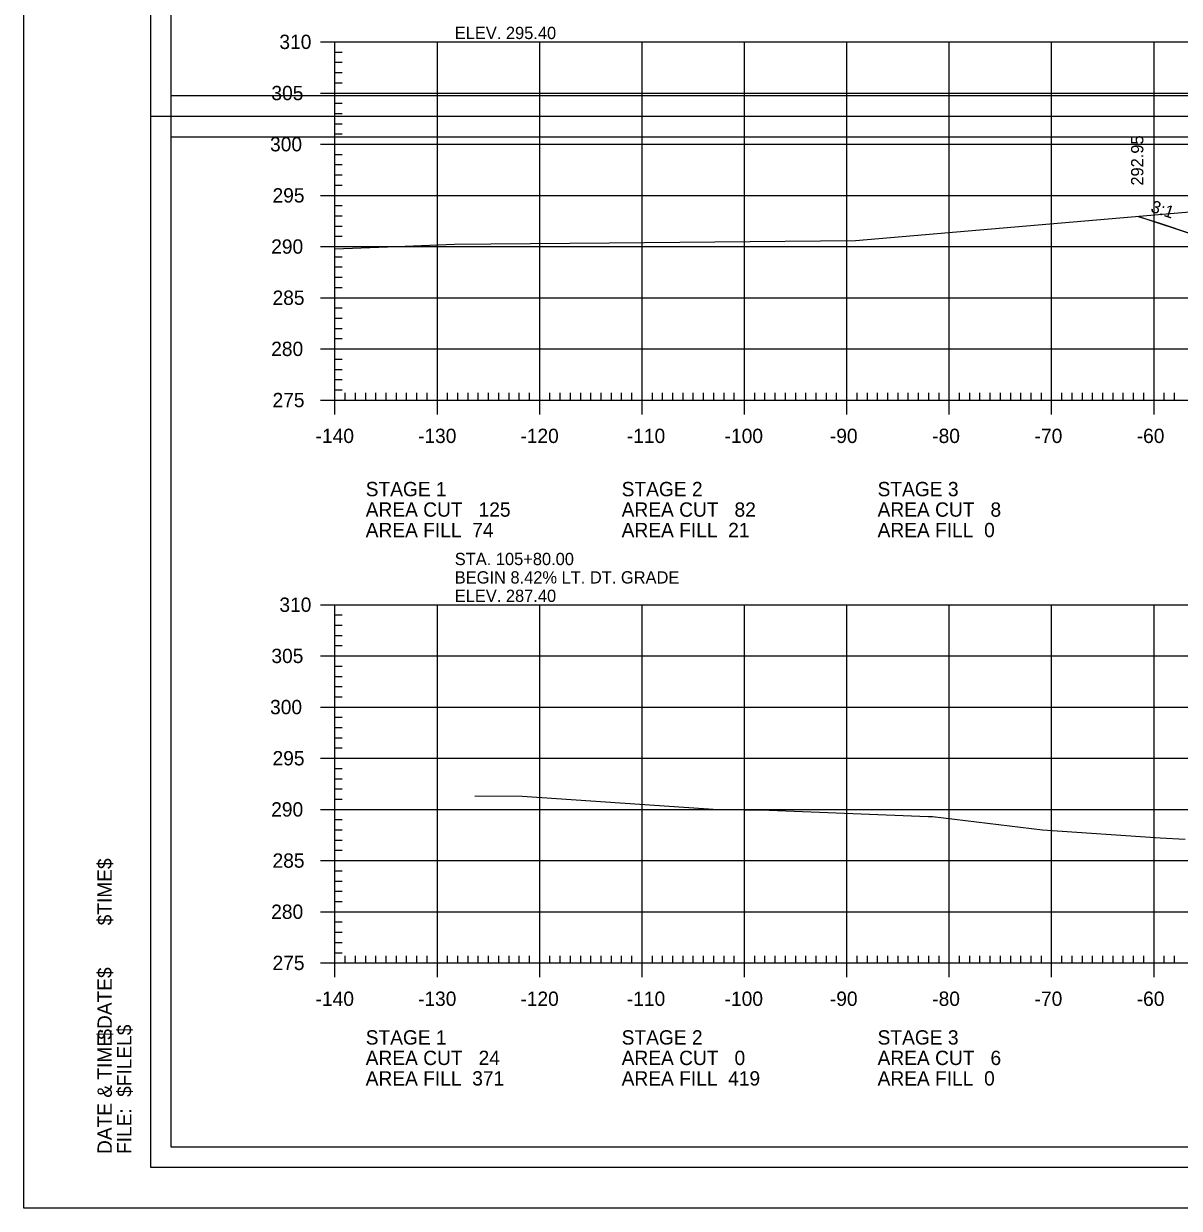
# Model space of a CAD drawing. Extents: x 1368713 to 1370673, y 380279 to 380950.
# Drawn here: x 1369981.9 to 1370094.8, y 380523.8 to 380639.5 of the extents above; entities that cross this region are included whole.
import ezdxf

# ---------------------------------------------------------------- set-up
doc = ezdxf.new("R2010")
doc.units = 0
for name, color, linetype in [('Notes', 7, 'Continuous'), ('R_Alt Surface', 7, 'Continuous'), ('R_Axis', 7, 'Continuous'), ('R_Axis Annot', 7, 'Continuous'), ('R_Border', 7, 'Continuous'), ('R_Border Notes', 7, 'Continuous'), ('R_Border Plan-Plan', 7, 'Continuous'), ('R_Exist Surface', 7, 'Continuous'), ('R_Fin Surface', 7, 'Continuous'), ('R_Grid', 7, 'Continuous'), ('R_No Plot', 7, 'Continuous'), ('R_Xsect Elev', 7, 'Continuous'), ('R_Xsect Slope', 7, 'Continuous')]:
    doc.layers.add(name, color=color, linetype=linetype)

msp = doc.modelspace()

# ---------------------------------------------------------------- linework, layer by layer
at = {"layer": 'R_Alt Surface'}
msp.add_lwpolyline([(1370102.34, 380616.84), (1370102.34, 380616.84), (1370090.74, 380620.7)], dxfattribs=at)
at = {"layer": 'R_Axis'}
for p, q in [((1370010.88, 380637.75), (1370013.68, 380637.75)), ((1370012.28, 380602.75), (1370012.28, 380637.75)), ((1370012.28, 380636.75), (1370012.98, 380636.75)), ((1370012.28, 380635.75), (1370012.98, 380635.75)), ((1370012.28, 380634.75), (1370012.98, 380634.75)), ((1370012.28, 380633.75), (1370012.98, 380633.75)), ((1370010.88, 380632.75), (1370013.68, 380632.75)), ((1370012.28, 380631.75), (1370012.98, 380631.75)), ((1370012.28, 380630.75), (1370012.98, 380630.75)), ((1370012.28, 380629.75), (1370012.98, 380629.75)), ((1370012.28, 380628.75), (1370012.98, 380628.75)), ((1370010.88, 380627.75), (1370013.68, 380627.75)), ((1370012.28, 380626.75), (1370012.98, 380626.75)), ((1370012.28, 380625.75), (1370012.98, 380625.75)), ((1370012.28, 380624.75), (1370012.98, 380624.75)), ((1370012.28, 380623.75), (1370012.98, 380623.75)), ((1370010.88, 380622.75), (1370013.68, 380622.75)), ((1370012.28, 380621.75), (1370012.98, 380621.75)), ((1370012.28, 380620.75), (1370012.98, 380620.75)), ((1370012.28, 380619.75), (1370012.98, 380619.75)), ((1370012.28, 380618.75), (1370012.98, 380618.75)), ((1370010.88, 380617.75), (1370013.68, 380617.75)), ((1370012.28, 380616.75), (1370012.98, 380616.75)), ((1370012.28, 380615.75), (1370012.98, 380615.75)), ((1370012.28, 380614.75), (1370012.98, 380614.75)), ((1370012.28, 380613.75), (1370012.98, 380613.75)), ((1370010.88, 380612.75), (1370013.68, 380612.75)), ((1370012.28, 380611.75), (1370012.98, 380611.75)), ((1370012.28, 380610.75), (1370012.98, 380610.75)), ((1370012.28, 380609.75), (1370012.98, 380609.75)), ((1370012.28, 380608.75), (1370012.98, 380608.75)), ((1370010.88, 380607.75), (1370013.68, 380607.75)), ((1370012.28, 380606.75), (1370012.98, 380606.75)), ((1370012.28, 380605.75), (1370012.98, 380605.75)), ((1370012.28, 380604.75), (1370012.98, 380604.75)), ((1370012.28, 380601.35), (1370012.28, 380604.15)), ((1370012.28, 380603.75), (1370012.98, 380603.75)), ((1370022.28, 380601.35), (1370022.28, 380604.15)), ((1370032.28, 380601.35), (1370032.28, 380604.15)), ((1370042.28, 380601.35), (1370042.28, 380604.15)), ((1370052.28, 380601.35), (1370052.28, 380604.15)), ((1370062.28, 380601.35), (1370062.28, 380604.15)), ((1370072.28, 380601.35), (1370072.28, 380604.15)), ((1370082.28, 380601.35), (1370082.28, 380604.15)), ((1370092.28, 380601.35), (1370092.28, 380604.15)), ((1370010.88, 380602.75), (1370013.68, 380602.75)), ((1370012.28, 380602.75), (1370292.28, 380602.75)), ((1370013.28, 380602.75), (1370013.28, 380603.45)), ((1370014.28, 380602.75), (1370014.28, 380603.45)), ((1370015.28, 380602.75), (1370015.28, 380603.45)), ((1370016.28, 380602.75), (1370016.28, 380603.45)), ((1370017.28, 380602.75), (1370017.28, 380603.45)), ((1370018.28, 380602.75), (1370018.28, 380603.45)), ((1370019.28, 380602.75), (1370019.28, 380603.45)), ((1370020.28, 380602.75), (1370020.28, 380603.45)), ((1370021.28, 380602.75), (1370021.28, 380603.45)), ((1370023.28, 380602.75), (1370023.28, 380603.45)), ((1370024.28, 380602.75), (1370024.28, 380603.45)), ((1370025.28, 380602.75), (1370025.28, 380603.45)), ((1370026.28, 380602.75), (1370026.28, 380603.45)), ((1370027.28, 380602.75), (1370027.28, 380603.45)), ((1370028.28, 380602.75), (1370028.28, 380603.45)), ((1370029.28, 380602.75), (1370029.28, 380603.45)), ((1370030.28, 380602.75), (1370030.28, 380603.45)), ((1370031.28, 380602.75), (1370031.28, 380603.45)), ((1370033.28, 380602.75), (1370033.28, 380603.45)), ((1370034.28, 380602.75), (1370034.28, 380603.45)), ((1370035.28, 380602.75), (1370035.28, 380603.45)), ((1370036.28, 380602.75), (1370036.28, 380603.45)), ((1370037.28, 380602.75), (1370037.28, 380603.45)), ((1370038.28, 380602.75), (1370038.28, 380603.45)), ((1370039.28, 380602.75), (1370039.28, 380603.45)), ((1370040.28, 380602.75), (1370040.28, 380603.45)), ((1370041.28, 380602.75), (1370041.28, 380603.45)), ((1370043.28, 380602.75), (1370043.28, 380603.45)), ((1370044.28, 380602.75), (1370044.28, 380603.45)), ((1370045.28, 380602.75), (1370045.28, 380603.45)), ((1370046.28, 380602.75), (1370046.28, 380603.45)), ((1370047.28, 380602.75), (1370047.28, 380603.45)), ((1370048.28, 380602.75), (1370048.28, 380603.45)), ((1370049.28, 380602.75), (1370049.28, 380603.45)), ((1370050.28, 380602.75), (1370050.28, 380603.45)), ((1370051.28, 380602.75), (1370051.28, 380603.45)), ((1370053.28, 380602.75), (1370053.28, 380603.45)), ((1370054.28, 380602.75), (1370054.28, 380603.45)), ((1370055.28, 380602.75), (1370055.28, 380603.45)), ((1370056.28, 380602.75), (1370056.28, 380603.45)), ((1370057.28, 380602.75), (1370057.28, 380603.45)), ((1370058.28, 380602.75), (1370058.28, 380603.45)), ((1370059.28, 380602.75), (1370059.28, 380603.45)), ((1370060.28, 380602.75), (1370060.28, 380603.45)), ((1370061.28, 380602.75), (1370061.28, 380603.45)), ((1370063.28, 380602.75), (1370063.28, 380603.45)), ((1370064.28, 380602.75), (1370064.28, 380603.45)), ((1370065.28, 380602.75), (1370065.28, 380603.45)), ((1370066.28, 380602.75), (1370066.28, 380603.45)), ((1370067.28, 380602.75), (1370067.28, 380603.45)), ((1370068.28, 380602.75), (1370068.28, 380603.45)), ((1370069.28, 380602.75), (1370069.28, 380603.45)), ((1370070.28, 380602.75), (1370070.28, 380603.45)), ((1370071.28, 380602.75), (1370071.28, 380603.45)), ((1370073.28, 380602.75), (1370073.28, 380603.45)), ((1370074.28, 380602.75), (1370074.28, 380603.45)), ((1370075.28, 380602.75), (1370075.28, 380603.45)), ((1370076.28, 380602.75), (1370076.28, 380603.45)), ((1370077.28, 380602.75), (1370077.28, 380603.45)), ((1370078.28, 380602.75), (1370078.28, 380603.45)), ((1370079.28, 380602.75), (1370079.28, 380603.45)), ((1370080.28, 380602.75), (1370080.28, 380603.45)), ((1370081.28, 380602.75), (1370081.28, 380603.45)), ((1370083.28, 380602.75), (1370083.28, 380603.45)), ((1370084.28, 380602.75), (1370084.28, 380603.45)), ((1370085.28, 380602.75), (1370085.28, 380603.45)), ((1370086.28, 380602.75), (1370086.28, 380603.45)), ((1370087.28, 380602.75), (1370087.28, 380603.45)), ((1370088.28, 380602.75), (1370088.28, 380603.45)), ((1370089.28, 380602.75), (1370089.28, 380603.45)), ((1370090.28, 380602.75), (1370090.28, 380603.45)), ((1370091.28, 380602.75), (1370091.28, 380603.45)), ((1370093.28, 380602.75), (1370093.28, 380603.45)), ((1370094.28, 380602.75), (1370094.28, 380603.45)), ((1370010.88, 380582.75), (1370013.68, 380582.75)), ((1370012.28, 380547.75), (1370012.28, 380582.75)), ((1370012.28, 380581.75), (1370012.98, 380581.75)), ((1370012.28, 380580.75), (1370012.98, 380580.75)), ((1370012.28, 380579.75), (1370012.98, 380579.75)), ((1370012.28, 380578.75), (1370012.98, 380578.75)), ((1370010.88, 380577.75), (1370013.68, 380577.75)), ((1370012.28, 380576.75), (1370012.98, 380576.75)), ((1370012.28, 380575.75), (1370012.98, 380575.75)), ((1370012.28, 380574.75), (1370012.98, 380574.75)), ((1370012.28, 380573.75), (1370012.98, 380573.75)), ((1370010.88, 380572.75), (1370013.68, 380572.75)), ((1370012.28, 380571.75), (1370012.98, 380571.75)), ((1370012.28, 380570.75), (1370012.98, 380570.75)), ((1370012.28, 380569.75), (1370012.98, 380569.75)), ((1370012.28, 380568.75), (1370012.98, 380568.75)), ((1370010.88, 380567.75), (1370013.68, 380567.75)), ((1370012.28, 380566.75), (1370012.98, 380566.75)), ((1370012.28, 380565.75), (1370012.98, 380565.75)), ((1370012.28, 380564.75), (1370012.98, 380564.75)), ((1370012.28, 380563.75), (1370012.98, 380563.75)), ((1370010.88, 380562.75), (1370013.68, 380562.75)), ((1370012.28, 380561.75), (1370012.98, 380561.75)), ((1370012.28, 380560.75), (1370012.98, 380560.75)), ((1370012.28, 380559.75), (1370012.98, 380559.75)), ((1370012.28, 380558.75), (1370012.98, 380558.75)), ((1370010.88, 380557.75), (1370013.68, 380557.75)), ((1370012.28, 380556.75), (1370012.98, 380556.75)), ((1370012.28, 380555.75), (1370012.98, 380555.75)), ((1370012.28, 380554.75), (1370012.98, 380554.75)), ((1370010.88, 380552.75), (1370013.68, 380552.75)), ((1370012.28, 380553.75), (1370012.98, 380553.75)), ((1370012.28, 380551.75), (1370012.98, 380551.75)), ((1370012.28, 380550.75), (1370012.98, 380550.75)), ((1370012.28, 380549.75), (1370012.98, 380549.75)), ((1370012.28, 380546.35), (1370012.28, 380549.15)), ((1370012.28, 380548.75), (1370012.98, 380548.75)), ((1370013.28, 380547.75), (1370013.28, 380548.45)), ((1370014.28, 380547.75), (1370014.28, 380548.45)), ((1370015.28, 380547.75), (1370015.28, 380548.45)), ((1370016.28, 380547.75), (1370016.28, 380548.45)), ((1370017.28, 380547.75), (1370017.28, 380548.45)), ((1370018.28, 380547.75), (1370018.28, 380548.45)), ((1370019.28, 380547.75), (1370019.28, 380548.45)), ((1370020.28, 380547.75), (1370020.28, 380548.45)), ((1370021.28, 380547.75), (1370021.28, 380548.45)), ((1370022.28, 380546.35), (1370022.28, 380549.15)), ((1370023.28, 380547.75), (1370023.28, 380548.45)), ((1370024.28, 380547.75), (1370024.28, 380548.45)), ((1370025.28, 380547.75), (1370025.28, 380548.45)), ((1370026.28, 380547.75), (1370026.28, 380548.45)), ((1370027.28, 380547.75), (1370027.28, 380548.45)), ((1370028.28, 380547.75), (1370028.28, 380548.45)), ((1370029.28, 380547.75), (1370029.28, 380548.45)), ((1370030.28, 380547.75), (1370030.28, 380548.45)), ((1370031.28, 380547.75), (1370031.28, 380548.45)), ((1370032.28, 380546.35), (1370032.28, 380549.15)), ((1370033.28, 380547.75), (1370033.28, 380548.45)), ((1370034.28, 380547.75), (1370034.28, 380548.45)), ((1370035.28, 380547.75), (1370035.28, 380548.45)), ((1370036.28, 380547.75), (1370036.28, 380548.45)), ((1370037.28, 380547.75), (1370037.28, 380548.45)), ((1370038.28, 380547.75), (1370038.28, 380548.45)), ((1370039.28, 380547.75), (1370039.28, 380548.45)), ((1370040.28, 380547.75), (1370040.28, 380548.45)), ((1370041.28, 380547.75), (1370041.28, 380548.45)), ((1370042.28, 380546.35), (1370042.28, 380549.15)), ((1370043.28, 380547.75), (1370043.28, 380548.45)), ((1370044.28, 380547.75), (1370044.28, 380548.45)), ((1370045.28, 380547.75), (1370045.28, 380548.45)), ((1370046.28, 380547.75), (1370046.28, 380548.45)), ((1370047.28, 380547.75), (1370047.28, 380548.45)), ((1370048.28, 380547.75), (1370048.28, 380548.45)), ((1370049.28, 380547.75), (1370049.28, 380548.45)), ((1370050.28, 380547.75), (1370050.28, 380548.45)), ((1370051.28, 380547.75), (1370051.28, 380548.45)), ((1370052.28, 380546.35), (1370052.28, 380549.15)), ((1370053.28, 380547.75), (1370053.28, 380548.45)), ((1370054.28, 380547.75), (1370054.28, 380548.45)), ((1370055.28, 380547.75), (1370055.28, 380548.45)), ((1370056.28, 380547.75), (1370056.28, 380548.45)), ((1370057.28, 380547.75), (1370057.28, 380548.45)), ((1370058.28, 380547.75), (1370058.28, 380548.45)), ((1370059.28, 380547.75), (1370059.28, 380548.45)), ((1370060.28, 380547.75), (1370060.28, 380548.45)), ((1370061.28, 380547.75), (1370061.28, 380548.45)), ((1370062.28, 380546.35), (1370062.28, 380549.15)), ((1370063.28, 380547.75), (1370063.28, 380548.45)), ((1370064.28, 380547.75), (1370064.28, 380548.45)), ((1370065.28, 380547.75), (1370065.28, 380548.45)), ((1370066.28, 380547.75), (1370066.28, 380548.45)), ((1370067.28, 380547.75), (1370067.28, 380548.45)), ((1370068.28, 380547.75), (1370068.28, 380548.45)), ((1370069.28, 380547.75), (1370069.28, 380548.45)), ((1370070.28, 380547.75), (1370070.28, 380548.45)), ((1370071.28, 380547.75), (1370071.28, 380548.45)), ((1370072.28, 380546.35), (1370072.28, 380549.15)), ((1370073.28, 380547.75), (1370073.28, 380548.45)), ((1370074.28, 380547.75), (1370074.28, 380548.45)), ((1370075.28, 380547.75), (1370075.28, 380548.45)), ((1370076.28, 380547.75), (1370076.28, 380548.45)), ((1370077.28, 380547.75), (1370077.28, 380548.45)), ((1370078.28, 380547.75), (1370078.28, 380548.45)), ((1370079.28, 380547.75), (1370079.28, 380548.45)), ((1370080.28, 380547.75), (1370080.28, 380548.45)), ((1370081.28, 380547.75), (1370081.28, 380548.45)), ((1370082.28, 380546.35), (1370082.28, 380549.15)), ((1370083.28, 380547.75), (1370083.28, 380548.45)), ((1370084.28, 380547.75), (1370084.28, 380548.45)), ((1370085.28, 380547.75), (1370085.28, 380548.45)), ((1370086.28, 380547.75), (1370086.28, 380548.45)), ((1370087.28, 380547.75), (1370087.28, 380548.45)), ((1370088.28, 380547.75), (1370088.28, 380548.45)), ((1370089.28, 380547.75), (1370089.28, 380548.45)), ((1370090.28, 380547.75), (1370090.28, 380548.45)), ((1370091.28, 380547.75), (1370091.28, 380548.45)), ((1370092.28, 380546.35), (1370092.28, 380549.15)), ((1370093.28, 380547.75), (1370093.28, 380548.45)), ((1370094.28, 380547.75), (1370094.28, 380548.45)), ((1370010.88, 380547.75), (1370013.68, 380547.75)), ((1370012.28, 380547.75), (1370292.28, 380547.75))]:
    msp.add_line(p, q, dxfattribs=at)
at = {"layer": 'R_Border'}
for p, q in [((1369994.28, 380527.75), (1369994.28, 380733.21)), ((1369994.28, 380527.75), (1369994.28, 380527.75)), ((1370310.46, 380527.75), (1369994.28, 380527.75))]:
    msp.add_line(p, q, dxfattribs=at)
at = {"layer": 'R_Border Plan-Plan'}
msp.add_line((1369994.28, 380630.48), (1370310.46, 380630.48), dxfattribs=at)
at = {"layer": 'R_Exist Surface'}
for points in [[(1370012.28, 380617.51), (1370019.15, 380617.8), (1370023.95, 380617.99), (1370027.49, 380618), (1370039.08, 380618.1), (1370063.12, 380618.34), (1370099.95, 380621.49)], [(1370025.94, 380564.06), (1370030.56, 380564.05), (1370037.28, 380563.59), (1370049.71, 380562.73), (1370054.7, 380562.69), (1370070.21, 380562.07), (1370070.31, 380562.07), (1370070.63, 380562.05), (1370081.39, 380560.75), (1370092.87, 380559.96), (1370095.32, 380559.84)]]:
    msp.add_lwpolyline(points, dxfattribs=at)
at = {"layer": 'R_Fin Surface'}
msp.add_lwpolyline([(1370090.74, 380620.7), (1370092.76, 380620.05), (1370102.34, 380616.84), (1370106.76, 380618.3), (1370127.28, 380625.15), (1370130.44, 380625.68), (1370137.28, 380626.82), (1370141.28, 380626.98), (1370152.28, 380627.2), (1370163.28, 380626.98), (1370167.28, 380626.82), (1370174.12, 380625.68), (1370177.28, 380625.15), (1370204.35, 380616.13), (1370222.68, 380622.26), (1370226.56, 380623.53)], dxfattribs=at)
at = {"layer": 'R_Grid'}
for p, q in [((1370012.28, 380637.75), (1370292.28, 380637.75)), ((1370012.28, 380602.75), (1370012.28, 380637.75)), ((1370022.28, 380602.75), (1370022.28, 380637.75)), ((1370032.28, 380602.75), (1370032.28, 380637.75)), ((1370042.28, 380602.75), (1370042.28, 380637.75)), ((1370052.28, 380602.75), (1370052.28, 380637.75)), ((1370062.28, 380602.75), (1370062.28, 380637.75)), ((1370072.28, 380602.75), (1370072.28, 380637.75)), ((1370082.28, 380602.75), (1370082.28, 380637.75)), ((1370092.28, 380602.75), (1370092.28, 380637.75)), ((1370012.28, 380632.75), (1370292.28, 380632.75)), ((1370012.28, 380627.75), (1370292.28, 380627.75)), ((1370012.28, 380622.75), (1370292.28, 380622.75)), ((1370012.28, 380617.75), (1370292.28, 380617.75)), ((1370012.28, 380612.75), (1370292.28, 380612.75)), ((1370012.28, 380607.75), (1370292.28, 380607.75)), ((1370012.28, 380602.75), (1370292.28, 380602.75)), ((1370012.28, 380582.75), (1370292.28, 380582.75)), ((1370012.28, 380547.75), (1370012.28, 380582.75)), ((1370022.28, 380547.75), (1370022.28, 380582.75)), ((1370032.28, 380547.75), (1370032.28, 380582.75)), ((1370042.28, 380547.75), (1370042.28, 380582.75)), ((1370052.28, 380547.75), (1370052.28, 380582.75)), ((1370062.28, 380547.75), (1370062.28, 380582.75)), ((1370072.28, 380547.75), (1370072.28, 380582.75)), ((1370082.28, 380547.75), (1370082.28, 380582.75)), ((1370092.28, 380547.75), (1370092.28, 380582.75)), ((1370012.28, 380577.75), (1370292.28, 380577.75)), ((1370012.28, 380572.75), (1370292.28, 380572.75)), ((1370012.28, 380567.75), (1370292.28, 380567.75)), ((1370012.28, 380562.75), (1370292.28, 380562.75)), ((1370012.28, 380557.75), (1370292.28, 380557.75)), ((1370012.28, 380552.75), (1370292.28, 380552.75)), ((1370012.28, 380547.75), (1370292.28, 380547.75))]:
    msp.add_line(p, q, dxfattribs=at)
at = {"layer": 'R_No Plot'}
for points in [[(1369981.88, 380737.11), (1370315.22, 380737.11), (1370315.22, 380523.77), (1369981.88, 380523.77)], [(1370308.46, 380632.48), (1369996.28, 380632.48), (1369996.28, 380731.21), (1370245.82, 380731.21), (1370245.82, 380721.33), (1370263.36, 380721.33), (1370287.46, 380721.33), (1370287.46, 380699), (1370308.46, 380699)], [(1369996.28, 380731.21), (1370245.82, 380731.21), (1370245.82, 380721.33), (1370263.36, 380721.33), (1370287.46, 380721.33), (1370287.46, 380699), (1370308.46, 380699), (1370308.46, 380529.75), (1369996.28, 380529.75)], [(1369996.28, 380628.48), (1370308.46, 380628.48), (1370308.46, 380529.75), (1369996.28, 380529.75)]]:
    msp.add_lwpolyline(points, close=True, dxfattribs=at)

# ---------------------------------------------------------------- texts
at = {"layer": 'Notes'}
for s, p in [('ELEV. 295.40', (1370023.98, 380638.02)), ('STA. 105+80.00', (1370023.98, 380586.62)), ('BEGIN 8.42% LT. DT. GRADE', (1370023.98, 380584.82)), ('ELEV. 287.40', (1370023.98, 380583.02))]:
    msp.add_text(s, height=1.2, dxfattribs=at).set_placement(p)
at = {"layer": 'R_Axis Annot'}
for s, p in [('310', (1370006.85, 380637.05)), ('305', (1370006.07, 380632.05)), ('300', (1370005.94, 380627.05)), ('295', (1370006.18, 380622.05)), ('290', (1370006.05, 380617.05)), ('285', (1370006.18, 380612.05)), ('280', (1370006.05, 380607.05)), ('275', (1370006.18, 380602.05)), ('-140', (1370010.39, 380598.55)), ('-130', (1370020.39, 380598.55)), ('-120', (1370030.39, 380598.55)), ('-110', (1370040.79, 380598.55)), ('-100', (1370050.34, 380598.55)), ('-90', (1370060.62, 380598.55)), ('-80', (1370070.62, 380598.55)), ('-70', (1370080.62, 380598.55)), ('-60', (1370090.59, 380598.55)), ('STAGE 1', (1370015.28, 380593.35)), ('STAGE 2', (1370040.28, 380593.35)), ('STAGE 3', (1370065.28, 380593.35)), ('AREA CUT   125', (1370015.28, 380591.35)), ('AREA CUT   82', (1370040.28, 380591.35)), ('AREA CUT   8', (1370065.28, 380591.35)), ('AREA FILL  74', (1370015.28, 380589.35)), ('AREA FILL  21', (1370040.28, 380589.35)), ('AREA FILL  0', (1370065.28, 380589.35)), ('310', (1370006.85, 380582.05)), ('305', (1370006.07, 380577.05)), ('300', (1370005.94, 380572.05)), ('295', (1370006.18, 380567.05)), ('290', (1370006.05, 380562.05)), ('285', (1370006.18, 380557.05)), ('280', (1370006.05, 380552.05)), ('275', (1370006.18, 380547.05)), ('-140', (1370010.39, 380543.55)), ('-130', (1370020.39, 380543.55)), ('-120', (1370030.39, 380543.55)), ('-110', (1370040.79, 380543.55)), ('-100', (1370050.34, 380543.55)), ('-90', (1370060.62, 380543.55)), ('-80', (1370070.62, 380543.55)), ('-70', (1370080.62, 380543.55)), ('-60', (1370090.59, 380543.55)), ('STAGE 1', (1370015.28, 380539.77)), ('STAGE 2', (1370040.28, 380539.77)), ('STAGE 3', (1370065.28, 380539.77)), ('AREA CUT   24', (1370015.28, 380537.77)), ('AREA CUT   0', (1370040.28, 380537.77)), ('AREA CUT   6', (1370065.28, 380537.77)), ('AREA FILL  371', (1370015.28, 380535.77)), ('AREA FILL  419', (1370040.28, 380535.77)), ('AREA FILL  0', (1370065.28, 380535.77))]:
    msp.add_text(s, height=1.4, dxfattribs=at).set_placement(p)
at = {"layer": 'R_Border Notes'}
for s, height, p in [('$TIME$', 1.397, (1369990.48, 380551.42)), ('$DATE$', 1.397, (1369990.48, 380540.25)), ('DATE & TIME:', 1.3968, (1369990.48, 380529.08)), ('$FILEL$', 1.397, (1369992.4, 380534.66)), ('FILE: ', 1.397, (1369992.4, 380529.08))]:
    msp.add_text(s, height=height, rotation=90, dxfattribs=at).set_placement(p)
at = {"layer": 'R_Xsect Elev'}
msp.add_text('292.95', height=1.2, rotation=90, dxfattribs=at).set_placement((1370091.24, 380623.7))
at = {"layer": 'R_Xsect Slope'}
msp.add_text('3:1', height=1.2, rotation=341.9374, dxfattribs=at).set_placement((1370091.88, 380621.16))

doc.saveas('drawing.dxf')
